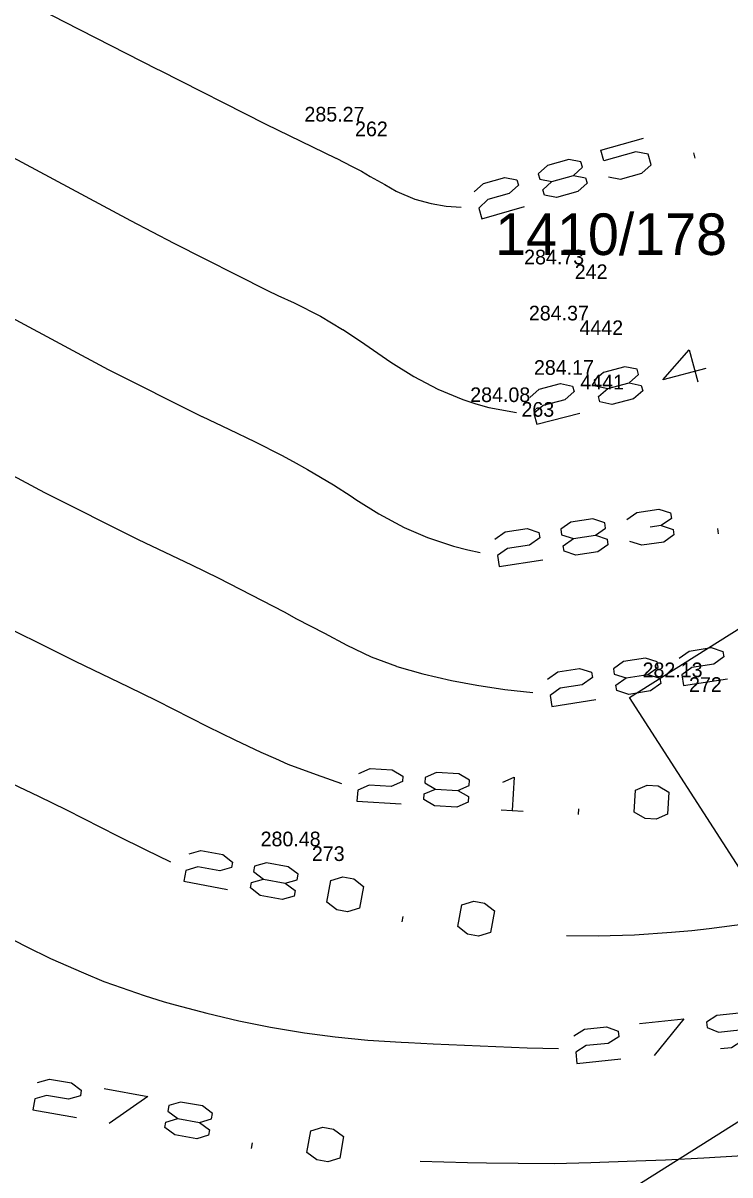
# Model space of a CAD drawing. Extents: x -771260 to -770828, y -1053564 to -1052811.
# Drawn here: x -771141.85 to -771112.94, y -1053143.24 to -1053096.13 of the extents above; entities that cross this region are included whole.
import ezdxf

# ---------------------------------------------------------------- set-up
doc = ezdxf.new("R2010")
doc.units = 0
for name, color, linetype in [('25_3_2019_vrstevnice_interval_po_1m', 7, 'Continuous'), ('25_3_2019_zamereny_bod', 7, 'Continuous'), ('25_3_2019_zamereny_bod_cislo', 7, 'Continuous'), ('25_3_2019_zamereny_bod_vyska', 7, 'Continuous'), ('Default', 7, 'Continuous'), ('DKM_Hranice parcel', 7, 'Continuous'), ('DKM_Parcelní čísla', 7, 'Continuous')]:
    doc.layers.add(name, color=color, linetype=linetype)

# ---------------------------------------------------------------- blocks, each defined once
blk = doc.blocks.new('POINT_DISPLAY')
at = {"layer": 'Default'}
blk.add_line((0, 0), (0, 0), dxfattribs=at)

msp = doc.modelspace()

# ---------------------------------------------------------------- linework, layer by layer
at = {"layer": '25_3_2019_vrstevnice_interval_po_1m'}
for points in [[(-771164.087, -1053083.487), (-771164.075, -1053083.494), (-771160.708, -1053085.319), (-771155.347, -1053088.187), (-771150.485, -1053090.744), (-771144.486, -1053093.856), (-771142.817, -1053094.707), (-771140.157, -1053096.084), (-771136.364, -1053098.016), (-771136.271, -1053098.063), (-771131.923, -1053100.263), (-771129.053, -1053101.654), (-771129.048, -1053101.657), (-771128.383, -1053102.002), (-771128.014, -1053102.193), (-771127.654, -1053102.403), (-771127.049, -1053102.738), (-771126.586, -1053103.005), (-771126.559, -1053103.021), (-771125.823, -1053103.33), (-771125.159, -1053103.519), (-771124.545, -1053103.624), (-771123.929, -1053103.666)], [(-771168.776, -1053087.342), (-771168.763, -1053087.349), (-771165.344, -1053089.131), (-771160.566, -1053091.665), (-771160.484, -1053091.709), (-771154.54, -1053094.928), (-771142.457, -1053101.522), (-771137.451, -1053104.205), (-771135.684, -1053105.13), (-771131.859, -1053107.066), (-771131.854, -1053107.069), (-771131.434, -1053107.274), (-771130.765, -1053107.58), (-771129.688, -1053108.126), (-771128.779, -1053108.661), (-771128.775, -1053108.663), (-771128.055, -1053109.142), (-771126.81, -1053110), (-771125.868, -1053110.595), (-771124.886, -1053111.103), (-771123.868, -1053111.535), (-771123.338, -1053111.71), (-771122.796, -1053111.853), (-771121.671, -1053112.059)], [(-771168.295, -1053094.166), (-771163.323, -1053096.749), (-771158.324, -1053099.418), (-771153.294, -1053102.153), (-771142.139, -1053108.267), (-771138.362, -1053110.296), (-771134.534, -1053112.226), (-771134.529, -1053112.228), (-771133.439, -1053112.738), (-771132.353, -1053113.267), (-771131.275, -1053113.81), (-771130.801, -1053114.063), (-771130.218, -1053114.395), (-771129.158, -1053115.022), (-771129.154, -1053115.024), (-771128.433, -1053115.484), (-771128.238, -1053115.616), (-771127.293, -1053116.204), (-771126.261, -1053116.764), (-771125.307, -1053117.175), (-771124.249, -1053117.524), (-771124.245, -1053117.525), (-771123.66, -1053117.673), (-771123.156, -1053117.784)], [(-771136.364, -1053098.016), (-771136.364, -1053098.016)], [(-771131.923, -1053100.263), (-771131.923, -1053100.263)], [(-771117.91, -1053102.428), (-771117.412, -1053102.523), (-771116.539, -1053102.275), (-771116.164, -1053101.932), (-771116.288, -1053101.496), (-771116.787, -1053101.401), (-771118.096, -1053101.773), (-771118.22, -1053101.337), (-771116.474, -1053100.841)], [(-771129.053, -1053101.654), (-771129.053, -1053101.654)], [(-771119.344, -1053102.364), (-771118.97, -1053102.021), (-771119.032, -1053101.803), (-771119.53, -1053101.709), (-771120.403, -1053101.957), (-771120.778, -1053102.299), (-771120.716, -1053102.517), (-771120.217, -1053102.612)], [(-771114.356, -1053101.655), (-771114.418, -1053101.436)], [(-771128.014, -1053102.193), (-771128.014, -1053102.193)], [(-771127.654, -1053102.403), (-771127.654, -1053102.403)], [(-771123.398, -1053103.043), (-771123.023, -1053102.701), (-771122.15, -1053102.453), (-771121.651, -1053102.547), (-771121.589, -1053102.765), (-771121.964, -1053103.108), (-771122.837, -1053103.356), (-771123.212, -1053103.698), (-771123.088, -1053104.135), (-771121.341, -1053103.639)], [(-771119.344, -1053102.364), (-771118.846, -1053102.458), (-771118.784, -1053102.676), (-771119.158, -1053103.019), (-771120.031, -1053103.267), (-771120.53, -1053103.172), (-771120.592, -1053102.954), (-771120.217, -1053102.612)], [(-771120.217, -1053102.612), (-771119.344, -1053102.364)], [(-771127.049, -1053102.738), (-771127.049, -1053102.738)], [(-771126.559, -1053103.021), (-771126.559, -1053103.021)], [(-771125.823, -1053103.33), (-771125.823, -1053103.33)], [(-771125.159, -1053103.519), (-771125.159, -1053103.519)], [(-771124.545, -1053103.624), (-771124.545, -1053103.624)], [(-771137.451, -1053104.205), (-771137.451, -1053104.205)], [(-771135.684, -1053105.13), (-771135.684, -1053105.13)], [(-771131.859, -1053107.066), (-771131.859, -1053107.066)], [(-771131.434, -1053107.274), (-771131.434, -1053107.274)], [(-771130.765, -1053107.58), (-771130.765, -1053107.58)], [(-771129.688, -1053108.126), (-771129.688, -1053108.126)], [(-771128.775, -1053108.663), (-771128.775, -1053108.663)], [(-771128.055, -1053109.142), (-771128.055, -1053109.142)], [(-771113.932, -1053110.257), (-771115.688, -1053110.719), (-771114.602, -1053109.494), (-771114.255, -1053110.811)], [(-771126.81, -1053110), (-771126.81, -1053110)], [(-771117.062, -1053110.846), (-771116.681, -1053110.511), (-771116.739, -1053110.291), (-771117.235, -1053110.188), (-771118.113, -1053110.419), (-771118.494, -1053110.754), (-771118.437, -1053110.973), (-771117.94, -1053111.077)], [(-771138.362, -1053110.296), (-771138.362, -1053110.296)], [(-771125.868, -1053110.595), (-771125.868, -1053110.595)], [(-771124.886, -1053111.103), (-771124.886, -1053111.103)], [(-771121.128, -1053111.447), (-771120.747, -1053111.112), (-771119.869, -1053110.881), (-771119.372, -1053110.985), (-771119.314, -1053111.204), (-771119.696, -1053111.539), (-771120.573, -1053111.77), (-771120.955, -1053112.105), (-771120.839, -1053112.544), (-771119.083, -1053112.082)], [(-771117.062, -1053110.846), (-771116.565, -1053110.95), (-771116.508, -1053111.169), (-771116.889, -1053111.504), (-771117.767, -1053111.735), (-771118.263, -1053111.631), (-771118.321, -1053111.412), (-771117.94, -1053111.077)], [(-771117.94, -1053111.077), (-771117.062, -1053110.846)], [(-771123.868, -1053111.535), (-771123.868, -1053111.535)], [(-771123.338, -1053111.71), (-771123.338, -1053111.71)], [(-771122.796, -1053111.853), (-771122.796, -1053111.853)], [(-771134.534, -1053112.226), (-771134.534, -1053112.226)], [(-771133.439, -1053112.738), (-771133.439, -1053112.738)], [(-771144.754, -1053113.309), (-771140.971, -1053115.327), (-771137.141, -1053117.253), (-771137.136, -1053117.256), (-771134.959, -1053118.293), (-771133.876, -1053118.827), (-771131.168, -1053120.219), (-771130.662, -1053120.499), (-771129.519, -1053121.086), (-771129.515, -1053121.088), (-771128.604, -1053121.573), (-771127.606, -1053122.048), (-771126.57, -1053122.441), (-771126.565, -1053122.443), (-771125.499, -1053122.75), (-771124.33, -1053123.022), (-771123.286, -1053123.213), (-771122.141, -1053123.392), (-771120.997, -1053123.518)], [(-771132.353, -1053113.267), (-771132.353, -1053113.267)], [(-771131.275, -1053113.81), (-771131.275, -1053113.81)], [(-771130.801, -1053114.063), (-771130.801, -1053114.063)], [(-771130.218, -1053114.395), (-771130.218, -1053114.395)], [(-771140.971, -1053115.327), (-771140.971, -1053115.327)], [(-771129.154, -1053115.024), (-771129.154, -1053115.024)], [(-771128.433, -1053115.484), (-771128.433, -1053115.484)], [(-771128.238, -1053115.616), (-771128.238, -1053115.616)], [(-771127.293, -1053116.204), (-771127.293, -1053116.204)], [(-771117.162, -1053116.435), (-771116.746, -1053116.144), (-771115.848, -1053116.011), (-771115.366, -1053116.169), (-771115.333, -1053116.393), (-771115.748, -1053116.685)], [(-771126.261, -1053116.764), (-771126.261, -1053116.764)], [(-771122.549, -1053117.235), (-771122.134, -1053116.944), (-771121.236, -1053116.811), (-771120.753, -1053116.969), (-771120.72, -1053117.193), (-771121.136, -1053117.484), (-771122.034, -1053117.617), (-771122.449, -1053117.909), (-771122.383, -1053118.357), (-771120.587, -1053118.091)], [(-771118.442, -1053117.084), (-771118.026, -1053116.793), (-771118.06, -1053116.569), (-771118.542, -1053116.411), (-771119.44, -1053116.544), (-771119.856, -1053116.835), (-771119.822, -1053117.06), (-771119.34, -1053117.218)], [(-771115.748, -1053116.685), (-771115.266, -1053116.842), (-771115.233, -1053117.067), (-771115.648, -1053117.358), (-771116.546, -1053117.491), (-771117.029, -1053117.333)], [(-771115.748, -1053116.685), (-771116.197, -1053116.751)], [(-771113.404, -1053117.025), (-771113.437, -1053116.8)], [(-771137.141, -1053117.253), (-771137.141, -1053117.253)], [(-771125.307, -1053117.175), (-771125.307, -1053117.175)], [(-771118.442, -1053117.084), (-771117.96, -1053117.242), (-771117.927, -1053117.467), (-771118.342, -1053117.758), (-771119.24, -1053117.891), (-771119.722, -1053117.733), (-771119.756, -1053117.509), (-771119.34, -1053117.218)], [(-771119.34, -1053117.218), (-771118.442, -1053117.084)], [(-771124.249, -1053117.524), (-771124.249, -1053117.524)], [(-771123.66, -1053117.673), (-771123.66, -1053117.673)], [(-771134.959, -1053118.293), (-771134.959, -1053118.293)], [(-771133.876, -1053118.827), (-771133.876, -1053118.827)], [(-771143.561, -1053120.322), (-771139.721, -1053122.231), (-771139.716, -1053122.233), (-771137.541, -1053123.274), (-771136.397, -1053123.842), (-771134.305, -1053124.902), (-771133.184, -1053125.45), (-771132.128, -1053125.951), (-771131.524, -1053126.204), (-771131.019, -1053126.436), (-771129.863, -1053126.869), (-771129.86, -1053126.87), (-771128.83, -1053127.232)], [(-771131.168, -1053120.219), (-771131.168, -1053120.219)], [(-771130.662, -1053120.499), (-771130.662, -1053120.499)], [(-771129.515, -1053121.088), (-771129.515, -1053121.088)], [(-771128.604, -1053121.573), (-771128.604, -1053121.573)], [(-771115.017, -1053122.112), (-771114.604, -1053121.817), (-771113.707, -1053121.675), (-771113.224, -1053121.828), (-771113.188, -1053122.052), (-771113.601, -1053122.347), (-771114.497, -1053122.489), (-771114.91, -1053122.784), (-771114.839, -1053123.232), (-771113.046, -1053122.949)], [(-771139.721, -1053122.231), (-771139.721, -1053122.231)], [(-771127.606, -1053122.048), (-771127.606, -1053122.048)], [(-771126.57, -1053122.441), (-771126.57, -1053122.441)], [(-771116.291, -1053122.773), (-771115.878, -1053122.478), (-771115.913, -1053122.254), (-771116.397, -1053122.101), (-771117.294, -1053122.242), (-771117.706, -1053122.538), (-771117.671, -1053122.762), (-771117.187, -1053122.915)], [(-771125.499, -1053122.75), (-771125.499, -1053122.75)], [(-771120.396, -1053122.963), (-771119.983, -1053122.668), (-771119.087, -1053122.526), (-771118.603, -1053122.68), (-771118.567, -1053122.904), (-771118.98, -1053123.199), (-771119.877, -1053123.341), (-771120.29, -1053123.636), (-771120.219, -1053124.084), (-771118.425, -1053123.8)], [(-771116.291, -1053122.773), (-771115.807, -1053122.926), (-771115.771, -1053123.15), (-771116.184, -1053123.445), (-771117.081, -1053123.587), (-771117.564, -1053123.434), (-771117.6, -1053123.21), (-771117.187, -1053122.915)], [(-771117.187, -1053122.915), (-771116.291, -1053122.773)], [(-771137.541, -1053123.274), (-771137.541, -1053123.274)], [(-771124.33, -1053123.022), (-771124.33, -1053123.022)], [(-771123.286, -1053123.213), (-771123.286, -1053123.213)], [(-771122.141, -1053123.392), (-771122.141, -1053123.392)], [(-771136.397, -1053123.842), (-771136.397, -1053123.842)], [(-771134.305, -1053124.902), (-771134.305, -1053124.902)], [(-771133.184, -1053125.45), (-771133.184, -1053125.45)], [(-771132.128, -1053125.951), (-771132.128, -1053125.951)], [(-771131.524, -1053126.204), (-771131.524, -1053126.204)], [(-771131.019, -1053126.436), (-771131.019, -1053126.436)], [(-771128.123, -1053126.819), (-771127.657, -1053126.62), (-771126.751, -1053126.675), (-771126.311, -1053126.928), (-771126.325, -1053127.155), (-771126.792, -1053127.354), (-771127.698, -1053127.3), (-771128.164, -1053127.499), (-771128.192, -1053127.952), (-771126.379, -1053128.061)], [(-771129.86, -1053126.87), (-771129.86, -1053126.87)], [(-771124.073, -1053127.518), (-771123.607, -1053127.318), (-771123.593, -1053127.092), (-771124.032, -1053126.838), (-771124.938, -1053126.784), (-771125.405, -1053126.983), (-771125.419, -1053127.209), (-771124.979, -1053127.463)], [(-771122.234, -1053127.174), (-771121.767, -1053126.974), (-771121.849, -1053128.333)], [(-771142.31, -1053127.236), (-771141.221, -1053127.747), (-771140.068, -1053128.304), (-771137.982, -1053129.37), (-771136.859, -1053129.931), (-771135.814, -1053130.437)], [(-771124.073, -1053127.518), (-771123.634, -1053127.771), (-771123.647, -1053127.998), (-771124.114, -1053128.197), (-771125.02, -1053128.143), (-771125.46, -1053127.889), (-771125.446, -1053127.662), (-771124.979, -1053127.463)], [(-771124.979, -1053127.463), (-771124.073, -1053127.518)], [(-771116.412, -1053128.66), (-771116.852, -1053128.407), (-771116.797, -1053127.5), (-771116.331, -1053127.301), (-771115.877, -1053127.328), (-771115.438, -1053127.582), (-771115.493, -1053128.488), (-771115.959, -1053128.688), (-771116.412, -1053128.66)], [(-771141.221, -1053127.747), (-771141.221, -1053127.747)], [(-771140.068, -1053128.304), (-771140.068, -1053128.304)], [(-771122.302, -1053128.306), (-771121.396, -1053128.361)], [(-771119.131, -1053128.497), (-771119.117, -1053128.27)], [(-771137.982, -1053129.37), (-771137.982, -1053129.37)], [(-771136.859, -1053129.931), (-771136.859, -1053129.931)], [(-771135.062, -1053130.115), (-771134.574, -1053129.975), (-771133.682, -1053130.141), (-771133.277, -1053130.447), (-771133.319, -1053130.671), (-771133.807, -1053130.811), (-771134.699, -1053130.645), (-771135.187, -1053130.785), (-771135.27, -1053131.231), (-771133.485, -1053131.563)], [(-771131.129, -1053131.309), (-771130.642, -1053131.168), (-771130.6, -1053130.945), (-771131.005, -1053130.639), (-771131.897, -1053130.473), (-771132.385, -1053130.613), (-771132.426, -1053130.837), (-771132.022, -1053131.143)], [(-771131.129, -1053131.309), (-771130.725, -1053131.615), (-771130.766, -1053131.838), (-771131.254, -1053131.978), (-771132.146, -1053131.812), (-771132.551, -1053131.506), (-771132.509, -1053131.283), (-771132.022, -1053131.143)], [(-771132.022, -1053131.143), (-771131.129, -1053131.309)], [(-771129.023, -1053132.393), (-771129.427, -1053132.087), (-771129.261, -1053131.194), (-771128.774, -1053131.054), (-771128.327, -1053131.137), (-771127.923, -1053131.443), (-771128.089, -1053132.336), (-771128.576, -1053132.476), (-771129.023, -1053132.393)], [(-771123.668, -1053133.389), (-771124.073, -1053133.083), (-771123.907, -1053132.19), (-771123.419, -1053132.05), (-771122.973, -1053132.133), (-771122.568, -1053132.439), (-771122.734, -1053133.332), (-771123.222, -1053133.472), (-771123.668, -1053133.389)], [(-771126.345, -1053132.891), (-771126.304, -1053132.668)], [(-771119.625, -1053133.448), (-771118.333, -1053133.469), (-771118.33, -1053133.468), (-771116.84, -1053133.427), (-771115.323, -1053133.316), (-771114.496, -1053133.238), (-771113.789, -1053133.158), (-771112.242, -1053132.963)], [(-771114.496, -1053133.238), (-771114.496, -1053133.238)], [(-771113.789, -1053133.158), (-771113.789, -1053133.158)], [(-771142.193, -1053133.657), (-771141.696, -1053133.911), (-771140.752, -1053134.374), (-771140.729, -1053134.384), (-771139.383, -1053134.979), (-771138.546, -1053135.325), (-771138.153, -1053135.471), (-771136.897, -1053135.903), (-771136.072, -1053136.161), (-771135.624, -1053136.291), (-771134.33, -1053136.631), (-771133.022, -1053136.939), (-771133.018, -1053136.939), (-771131.73, -1053137.201), (-771130.337, -1053137.433), (-771129.09, -1053137.594), (-771127.743, -1053137.725), (-771126.379, -1053137.815), (-771126.087, -1053137.83), (-771125.08, -1053137.881), (-771121.237, -1053138.039), (-771119.948, -1053138.069)], [(-771119.625, -1053133.448), (-771119.625, -1053133.448)], [(-771118.333, -1053133.469), (-771118.333, -1053133.469)], [(-771116.84, -1053133.427), (-771116.84, -1053133.427)], [(-771115.323, -1053133.316), (-771115.323, -1053133.316)], [(-771141.696, -1053133.911), (-771141.696, -1053133.911)], [(-771140.752, -1053134.374), (-771140.752, -1053134.374)], [(-771139.383, -1053134.979), (-771139.383, -1053134.979)], [(-771138.546, -1053135.325), (-771138.546, -1053135.325)], [(-771138.153, -1053135.471), (-771138.153, -1053135.471)], [(-771136.897, -1053135.903), (-771136.897, -1053135.903)], [(-771136.072, -1053136.161), (-771136.072, -1053136.161)], [(-771135.624, -1053136.291), (-771135.624, -1053136.291)], [(-771134.33, -1053136.631), (-771134.33, -1053136.631)], [(-771133.022, -1053136.939), (-771133.022, -1053136.939)], [(-771116.632, -1053137.044), (-771114.826, -1053136.858), (-771116.041, -1053138.352)], [(-771113.332, -1053138.073), (-771112.881, -1053138.027), (-771112.024, -1053137.482), (-771112.094, -1053136.805), (-771112.569, -1053136.626), (-771113.472, -1053136.719), (-771113.9, -1053136.991), (-771113.877, -1053137.217), (-771113.402, -1053137.396), (-771112.047, -1053137.256)], [(-771131.73, -1053137.201), (-771131.73, -1053137.201)], [(-771130.337, -1053137.433), (-771130.337, -1053137.433)], [(-771119.318, -1053137.548), (-771118.889, -1053137.276), (-771117.986, -1053137.183), (-771117.512, -1053137.362), (-771117.488, -1053137.588), (-771117.917, -1053137.86), (-771118.82, -1053137.953), (-771119.248, -1053138.225), (-771119.201, -1053138.677), (-771117.396, -1053138.491)], [(-771129.09, -1053137.594), (-771129.09, -1053137.594)], [(-771127.743, -1053137.725), (-771127.743, -1053137.725)], [(-771126.379, -1053137.815), (-771126.379, -1053137.815)], [(-771125.08, -1053137.881), (-771125.08, -1053137.881)], [(-771121.237, -1053138.039), (-771121.237, -1053138.039)], [(-771141.255, -1053139.463), (-771140.768, -1053139.319), (-771139.874, -1053139.476), (-771139.467, -1053139.778), (-771139.506, -1053140.002), (-771139.992, -1053140.146), (-771140.886, -1053139.989), (-771141.373, -1053140.134), (-771141.452, -1053140.581), (-771139.664, -1053140.896)], [(-771138.533, -1053139.712), (-771136.745, -1053140.027), (-771138.323, -1053141.132)], [(-771134.629, -1053141.091), (-771134.142, -1053140.946), (-771134.103, -1053140.723), (-771134.511, -1053140.421), (-771135.405, -1053140.263), (-771135.891, -1053140.408), (-771135.93, -1053140.631), (-771135.523, -1053140.934)], [(-771134.629, -1053141.091), (-771134.221, -1053141.393), (-771134.26, -1053141.617), (-771134.747, -1053141.762), (-771135.641, -1053141.604), (-771136.048, -1053141.302), (-771136.009, -1053141.078), (-771135.523, -1053140.934)], [(-771135.523, -1053140.934), (-771134.629, -1053141.091)], [(-771129.83, -1053142.627), (-771130.237, -1053142.325), (-771130.08, -1053141.431), (-771129.594, -1053141.286), (-771129.147, -1053141.365), (-771128.739, -1053141.667), (-771128.896, -1053142.561), (-771129.383, -1053142.706), (-771129.83, -1053142.627)], [(-771132.512, -1053142.155), (-771132.472, -1053141.932)], [(-771125.607, -1053142.68), (-771123.677, -1053142.726), (-771122.89, -1053142.744), (-771121.597, -1053142.764), (-771121.595, -1053142.764), (-771120.12, -1053142.768), (-771118.631, -1053142.737), (-771116.77, -1053142.666), (-771115.581, -1053142.62), (-771114.009, -1053142.541), (-771112.419, -1053142.445)], [(-771125.607, -1053142.68), (-771125.607, -1053142.68)], [(-771115.581, -1053142.62), (-771115.581, -1053142.62)], [(-771114.009, -1053142.541), (-771114.009, -1053142.541)], [(-771122.89, -1053142.744), (-771122.89, -1053142.744)], [(-771121.597, -1053142.764), (-771121.597, -1053142.764)], [(-771120.12, -1053142.768), (-771120.12, -1053142.768)], [(-771118.631, -1053142.737), (-771118.631, -1053142.737)]]:
    msp.add_lwpolyline(points, dxfattribs=at)
at = {"layer": 'DKM_Hranice parcel'}
msp.add_line((-771138.1, -1053157.08), (-771107.81, -1053138.05), dxfattribs=at)
msp.add_lwpolyline([(-771107.81, -1053138.05), (-771117.05, -1053123.71), (-771080.25, -1053100.58)], dxfattribs=at)

# ---------------------------------------------------------------- block references
at = {"layer": '25_3_2019_zamereny_bod', "xscale": 0.1, "yscale": 0.10000000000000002}
for p in [(-771128.273, -1053100.162), (-771119.286, -1053106.003), (-771119.094, -1053108.295), (-771119.058, -1053110.52), (-771121.465, -1053111.634), (-771114.613, -1053122.885), (-771130.038, -1053129.802)]:
    msp.add_blockref('POINT_DISPLAY', p, dxfattribs=at)

# ---------------------------------------------------------------- texts
at = {"layer": '25_3_2019_zamereny_bod_cislo'}
for s, p in [('262', (-771128.273, -1053100.762)), ('242', (-771119.286, -1053106.603)), ('4442', (-771119.094, -1053108.895)), ('4441', (-771119.058, -1053111.12)), ('263', (-771121.465, -1053112.234)), ('272', (-771114.613, -1053123.485)), ('273', (-771130.038, -1053130.402))]:
    msp.add_text(s, height=0.6, dxfattribs=at).set_placement(p)
at = {"layer": '25_3_2019_zamereny_bod_vyska'}
for s, p in [('285.27 ', (-771130.341, -1053100.162)), ('284.73 ', (-771121.356, -1053106.003)), ('284.37 ', (-771121.162, -1053108.295)), ('284.17 ', (-771120.955, -1053110.52)), ('284.08 ', (-771123.561, -1053111.634)), ('282.13 ', (-771116.512, -1053122.885)), ('280.48 ', (-771132.134, -1053129.802))]:
    msp.add_text(s, height=0.6, dxfattribs=at).set_placement(p)
at = {"layer": 'DKM_Parcelní čísla'}
msp.add_text('1410/178', height=1.7, dxfattribs=at).set_placement((-771122.54, -1053105.62))

doc.saveas('drawing.dxf')
